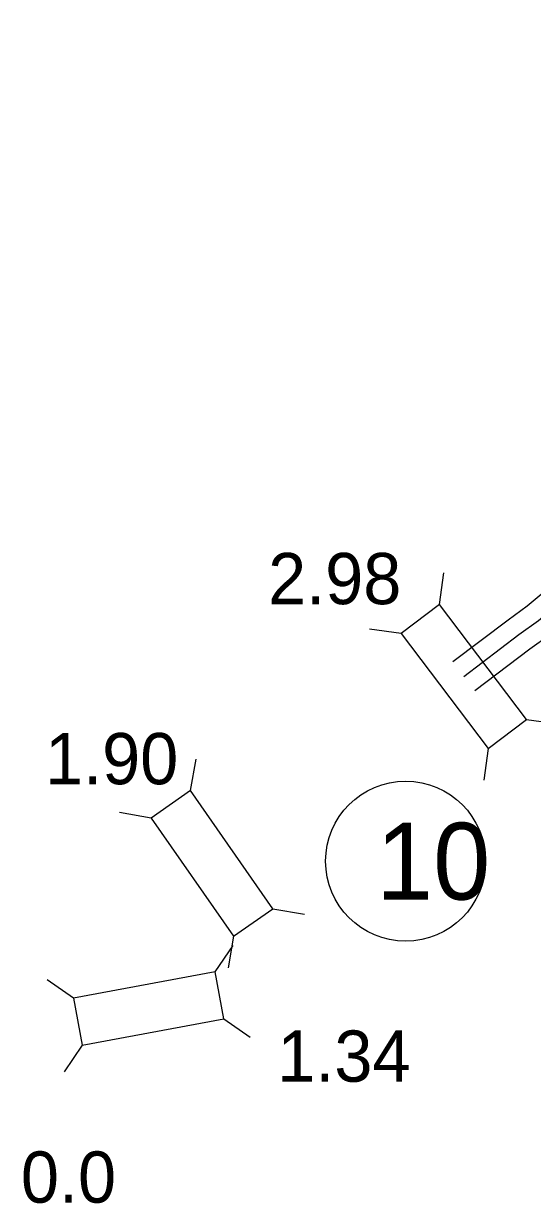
# Model space of a CAD drawing. Extents: x 31699 to 244310, y -8841 to 11474.
# Drawn here: x 93992 to 94272, y 1544 to 2192 of the extents above; entities that cross this region are included whole.
import ezdxf

# ---------------------------------------------------------------- set-up
doc = ezdxf.new("R2010")
doc.units = 0
for name, color, linetype in [('B_Logo', 7, 'Continuous'), ('R_Border Notes', 7, 'Continuous'), ('R_XS_EARTHWORK_STAGE1', 7, 'Continuous'), ('R_XS_EARTHWORK_STAGE2', 7, 'Continuous'), ('S_WALL', 7, 'Continuous'), ('S_WALL_ANNOT', 7, 'Continuous')]:
    doc.layers.add(name, color=color, linetype=linetype)

msp = doc.modelspace()

# ---------------------------------------------------------------- linework, layer by layer
at = {"layer": 'B_Logo'}
msp.add_lwpolyline([(94234.55, 1833.28), (94264.86, 1856.25), (94275.52, 1863.94), (94284.51, 1871.46), (94345.62, 1919.02), (94381.93, 1941.98), (94458.38, 2006.87), (94485.93, 2030.59), (94488.46, 2034.11), (94492.53, 2041.21), (94496.18, 2048.89), (94536.88, 2156.16), (94539.82, 2162.77), (94544.68, 2170.08), (94549.77, 2176.12), (94572.07, 2198.74)], dxfattribs=at)
at = {"layer": 'R_Border Notes'}
msp.add_circle((94202.53, 1731.73), 44, dxfattribs=at)
at = {"layer": 'R_XS_EARTHWORK_STAGE1'}
for p, q in [((94221.16, 1872.82), (94223.57, 1890.26)), ((94200.12, 1856.88), (94182.68, 1859.29)), ((94268.98, 1809.69), (94286.41, 1807.28)), ((94247.94, 1793.75), (94245.53, 1776.31)), ((94084.19, 1770.5), (94087.25, 1787.83)), ((94062.55, 1755.37), (94045.22, 1758.43)), ((94129.58, 1705.6), (94146.91, 1702.54)), ((94107.95, 1690.47), (94104.88, 1673.14)), ((94097.75, 1670.94), (94107.71, 1685.45)), ((94019.88, 1656.47), (94005.37, 1666.43)), ((94102.57, 1644.98), (94117.08, 1635.02)), ((94024.7, 1630.52), (94014.74, 1616.01))]:
    msp.add_line(p, q, dxfattribs=at)
for points in [[(94268.98, 1809.69), (94221.16, 1872.82), (94200.12, 1856.88), (94247.94, 1793.75)], [(94129.58, 1705.6), (94084.19, 1770.5), (94062.55, 1755.37), (94107.95, 1690.47)], [(94097.75, 1670.94), (94019.88, 1656.47), (94024.7, 1630.52), (94102.57, 1644.98)]]:
    msp.add_lwpolyline(points, close=True, dxfattribs=at)
at = {"layer": 'R_XS_EARTHWORK_STAGE2'}
for points in [[(94564.95, 2205.76), (94542.37, 2182.86), (94536.67, 2176.08), (94531.03, 2167.6), (94527.63, 2159.97), (94486.97, 2052.82), (94483.66, 2045.84), (94480.04, 2039.53), (94478.51, 2037.39), (94451.88, 2014.47), (94375.99, 1950.05), (94339.87, 1927.21), (94278.23, 1879.24), (94269.38, 1871.84), (94258.92, 1864.29), (94228.51, 1841.26)], [(94579.19, 2191.72), (94557.16, 2169.38), (94552.7, 2164.07), (94548.62, 2157.93), (94546.13, 2152.36), (94505.38, 2044.97), (94501.39, 2036.57), (94496.88, 2028.69), (94493.36, 2023.79), (94464.88, 1999.27), (94387.87, 1933.9), (94351.38, 1910.83), (94290.79, 1863.68), (94281.66, 1856.04), (94270.81, 1848.2), (94240.59, 1825.31)]]:
    msp.add_lwpolyline(points, dxfattribs=at)

# ---------------------------------------------------------------- texts
at = {"layer": 'R_Border Notes'}
msp.add_text('10', height=42.24, dxfattribs=at).set_placement((94186.25, 1710.61))
at = {"layer": 'S_WALL'}
for s, p in [('2.98', (94126.87, 1873)), ('1.90', (94004.19, 1774.02)), ('1.34', (94131.92, 1610.51))]:
    msp.add_text(s, height=28.16, dxfattribs=at).set_placement(p)
at = {"layer": 'S_WALL_ANNOT'}
msp.add_text('0.0', height=28.16, dxfattribs=at).set_placement((93990.94, 1544.01))

doc.saveas('drawing.dxf')
